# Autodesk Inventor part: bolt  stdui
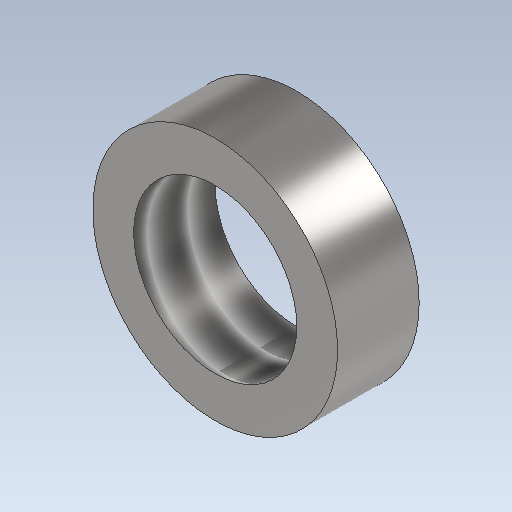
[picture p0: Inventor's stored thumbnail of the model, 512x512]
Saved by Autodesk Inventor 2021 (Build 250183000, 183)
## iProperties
Created: 2021-07
Part Number: bolt  stdui
Material: Steel, Mild
Document SubType Name: Sheet Metal
Designer: user
Density: 7.85 g/cm^3
Sheet Metal Rule: Default_mm
Appearance: Semi-Polished
Author: user
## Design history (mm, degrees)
sketch "Sketch1"
  geometry: C1 r 0.75 at (0, 0); 1 further point
  constraints: 1 centre point, 1 coincident
  dimensions: "d0" = 1.5 diameter of C1
sketch "Sketch2"
  geometry: 1 further point
extrude "Extrusion1" new body sketch "Sketch1" distance "d1" = 0.5; taper "d2" = 0 deg
sketch "Sketch3"
  geometry: C1 r 0.5 at (0, 0); 1 further point
  constraints: 1 centre point, 1 coincident
  dimensions: "d3" = 1 diameter of C1
cut "Cut1" sketch "Sketch3" dims "d5" = 0.5 (= Thickness), "d6" = 0
thread "Thread1" dims "d7" = 9.9568, "d8" = 0
body "Solid1"
other parameters: "Thickness" = 0.5, "BendRadius" = 0.5 (= Thickness), "BendReliefWidth" = 0.5 (= Thickness), "BendReliefDepth" = 0.25 (= 0.5 x Thickness), "CornerReliefSize" = 2 (= 4 x Thickness), "SeamGap" = 0.01, "MinimumRemnant" = 1 (= 2 x Thickness), "TransitionRadius" = 0.5 (= BendRadius), "JacobiRadiusSize" = 0.5 (= BendRadius), "GapSize" = 0.5 (= Thickness), "d4" = 0.5 (= Thickness)
